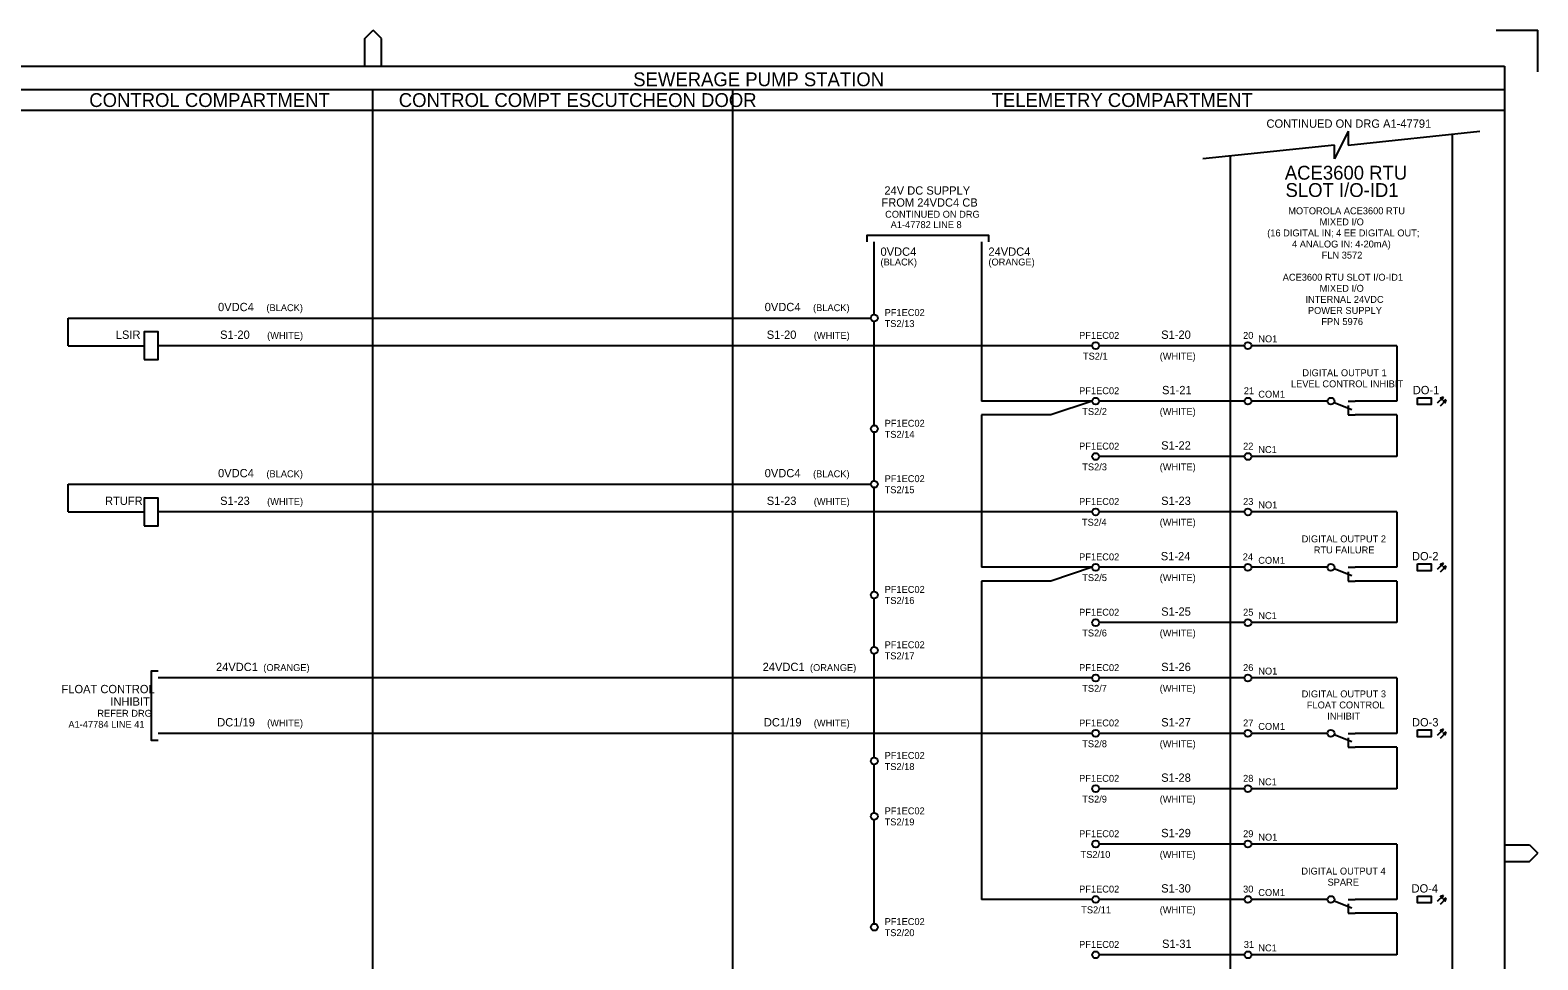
# Model space of a CAD drawing. Extents: x 0 to 841, y 0 to 594.
# Drawn here: x 296 to 841, y 258 to 594 of the extents above; entities that cross this region are included whole.
import ezdxf

# ---------------------------------------------------------------- set-up
doc = ezdxf.new("R2010")
doc.units = 0
for name, color, linetype in [('A1BORDER', 7, 'Continuous'), ('Level 1', 7, 'Continuous'), ('Level 10', 7, 'Continuous'), ('Level 2', 7, 'Continuous')]:
    doc.layers.add(name, color=color, linetype=linetype)

msp = doc.modelspace()

# ---------------------------------------------------------------- linework, layer by layer
at = {"layer": 'A1BORDER'}
for p, q in [((417.19, 591), (420.19, 594)), ((423.19, 591), (420.19, 594)), ((826, 594), (841, 594)), ((841, 579), (841, 594)), ((417.19, 581), (417.19, 591)), ((423.19, 581), (423.19, 591)), ((28, 581), (829, 581)), ((829, 581), (829, 15)), ((829, 299.76), (838, 299.76)), ((838, 299.76), (841, 296.76)), ((838, 293.76), (841, 296.76)), ((829, 293.76), (838, 293.76))]:
    msp.add_line(p, q, dxfattribs=at)
at = {"layer": 'Level 1'}
for p, q in [((829, 572.5), (160, 572.5)), ((420, 572.5), (420, 57)), ((550, 572.5), (550, 57)), ((829, 565), (160, 565)), ((772.5, 557.5), (767.5, 547.5)), ((772.5, 557.5), (772.5, 552.5)), ((772.5, 552.5), (820, 557.5)), ((767.5, 552.5), (720, 547.5)), ((767.5, 547.5), (767.5, 552.5)), ((601.25, 491.25), (601.25, 517.5)), ((640, 517.5), (640, 460)), ((310, 490), (600, 490)), ((310, 480), (310, 490)), ((601.25, 451.25), (601.25, 488.75)), ((310, 480), (337.5, 480)), ((680, 480), (342.5, 480)), ((735, 480), (682.5, 480)), ((790, 480), (737.5, 480)), ((790, 480), (790, 460)), ((680, 460), (640, 460)), ((680, 460), (665, 455)), ((735, 460), (682.5, 460)), ((765, 460), (737.5, 460)), ((790, 460), (775, 460)), ((665, 455), (640, 455)), ((640, 455), (640, 400)), ((790, 455), (775, 455)), ((790, 455), (790, 440)), ((601.25, 431.25), (601.25, 448.75)), ((735, 440), (682.5, 440)), ((790, 440), (737.5, 440)), ((310, 430), (600, 430)), ((310, 420), (310, 430)), ((601.25, 391.25), (601.25, 428.75)), ((310, 420), (337.5, 420)), ((680, 420), (342.5, 420)), ((735, 420), (682.5, 420)), ((790, 420), (737.5, 420)), ((790, 420), (790, 400)), ((680, 400), (640, 400)), ((680, 400), (665, 395)), ((735, 400), (682.5, 400)), ((765, 400), (737.5, 400)), ((790, 400), (775, 400)), ((665, 395), (640, 395)), ((640, 395), (640, 280)), ((790, 395), (775, 395)), ((790, 395), (790, 380)), ((601.25, 371.25), (601.25, 388.75)), ((735, 380), (682.5, 380)), ((790, 380), (737.5, 380)), ((601.25, 331.25), (601.25, 368.75)), ((680, 360), (342.5, 360)), ((735, 360), (682.5, 360)), ((790, 360), (737.5, 360)), ((790, 360), (790, 340)), ((680, 340), (342.5, 340)), ((735, 340), (682.5, 340)), ((765, 340), (737.5, 340)), ((790, 340), (775, 340)), ((790, 335), (775, 335)), ((790, 335), (790, 320)), ((601.25, 311.25), (601.25, 328.75)), ((735, 320), (682.5, 320)), ((790, 320), (737.5, 320)), ((601.25, 271.25), (601.25, 308.75)), ((735, 300), (682.5, 300)), ((790, 300), (737.5, 300)), ((790, 300), (790, 280)), ((680, 280), (640, 280)), ((735, 280), (682.5, 280)), ((765, 280), (737.5, 280)), ((790, 280), (775, 280)), ((790, 275), (775, 275)), ((790, 275), (790, 260)), ((735, 260), (682.5, 260)), ((790, 260), (737.5, 260))]:
    msp.add_line(p, q, dxfattribs=at)
for points in [[(810, 556.45), (810, 80), (730, 80), (730, 548.55)], [(598.75, 517.5), (598.75, 520), (642.5, 520), (642.5, 517.5)], [(342.5, 362.5), (340, 362.5), (340, 337.5), (342.5, 337.5)]]:
    msp.add_lwpolyline(points, dxfattribs=at)
for points in [[(337.5, 475), (342.5, 475), (342.5, 485), (337.5, 485)], [(797.5, 461.25), (802.5, 461.25), (802.5, 458.75), (797.5, 458.75)], [(337.5, 415), (342.5, 415), (342.5, 425), (337.5, 425)], [(797.5, 401.25), (802.5, 401.25), (802.5, 398.75), (797.5, 398.75)], [(797.5, 341.25), (802.5, 341.25), (802.5, 338.75), (797.5, 338.75)], [(797.5, 281.25), (802.5, 281.25), (802.5, 278.75), (797.5, 278.75)]]:
    msp.add_lwpolyline(points, close=True, dxfattribs=at)
at = {"layer": 'Level 10'}
for p, q in [((767.41, 459.54), (773.75, 457)), ((772.5, 460), (775, 460)), ((772.5, 458.37), (772.5, 455)), ((804.73, 459.35), (806.86, 461.48)), ((805.79, 458.29), (807.91, 460.42)), ((805.96, 461.07), (806.67, 461.07)), ((806, 460.92), (806.61, 460.92)), ((806.14, 460.77), (806.53, 460.77)), ((806.29, 461.22), (806.74, 461.22)), ((806.3, 460.62), (806.47, 460.62)), ((806.62, 461.37), (806.81, 461.37)), ((807.02, 460.01), (807.73, 460.01)), ((807.06, 459.86), (807.66, 459.86)), ((807.21, 459.71), (807.6, 459.71)), ((807.35, 460.16), (807.8, 460.16)), ((807.36, 459.56), (807.53, 459.56)), ((807.68, 460.31), (807.87, 460.31)), ((772.5, 455), (775, 455)), ((767.41, 399.54), (773.75, 397)), ((772.5, 400), (775, 400)), ((772.5, 398.37), (772.5, 395)), ((804.73, 399.35), (806.86, 401.48)), ((805.79, 398.29), (807.91, 400.42)), ((805.96, 401.07), (806.67, 401.07)), ((806, 400.92), (806.61, 400.92)), ((806.14, 400.77), (806.53, 400.77)), ((806.29, 401.22), (806.74, 401.22)), ((806.3, 400.62), (806.47, 400.62)), ((806.62, 401.37), (806.81, 401.37)), ((807.02, 400.01), (807.73, 400.01)), ((807.06, 399.86), (807.66, 399.86)), ((807.21, 399.71), (807.6, 399.71)), ((807.35, 400.16), (807.8, 400.16)), ((807.36, 399.56), (807.53, 399.56)), ((807.68, 400.31), (807.87, 400.31)), ((772.5, 395), (775, 395)), ((767.41, 339.54), (773.75, 337)), ((772.5, 340), (775, 340)), ((772.5, 338.37), (772.5, 335)), ((804.73, 339.35), (806.86, 341.48)), ((805.79, 338.29), (807.91, 340.42)), ((805.96, 341.07), (806.67, 341.07)), ((806, 340.92), (806.61, 340.92)), ((806.14, 340.77), (806.53, 340.77)), ((806.29, 341.22), (806.74, 341.22)), ((806.3, 340.62), (806.47, 340.62)), ((806.62, 341.37), (806.81, 341.37)), ((807.02, 340.01), (807.73, 340.01)), ((807.06, 339.86), (807.66, 339.86)), ((807.21, 339.71), (807.6, 339.71)), ((807.35, 340.16), (807.8, 340.16)), ((807.36, 339.56), (807.53, 339.56)), ((807.68, 340.31), (807.87, 340.31)), ((772.5, 335), (775, 335)), ((767.41, 279.54), (773.75, 277)), ((772.5, 280), (775, 280)), ((772.5, 278.37), (772.5, 275)), ((804.73, 279.35), (806.86, 281.48)), ((805.79, 278.29), (807.91, 280.42)), ((805.96, 281.07), (806.67, 281.07)), ((806, 280.92), (806.61, 280.92)), ((806.14, 280.77), (806.53, 280.77)), ((806.29, 281.22), (806.74, 281.22)), ((806.3, 280.62), (806.47, 280.62)), ((806.62, 281.37), (806.81, 281.37)), ((807.02, 280.01), (807.73, 280.01)), ((807.06, 279.86), (807.66, 279.86)), ((807.21, 279.71), (807.6, 279.71)), ((807.35, 280.16), (807.8, 280.16)), ((807.36, 279.56), (807.53, 279.56)), ((807.68, 280.31), (807.87, 280.31)), ((772.5, 275), (775, 275))]:
    msp.add_line(p, q, dxfattribs=at)
for points in [[(806.86, 461.48), (805.88, 461.04), (806.41, 460.5)], [(807.91, 460.42), (806.94, 459.98), (807.48, 459.44)], [(806.86, 401.48), (805.88, 401.04), (806.41, 400.5)], [(807.91, 400.42), (806.94, 399.98), (807.48, 399.44)], [(806.86, 341.48), (805.88, 341.04), (806.41, 340.5)], [(807.91, 340.42), (806.94, 339.98), (807.48, 339.44)], [(806.86, 281.48), (805.88, 281.04), (806.41, 280.5)], [(807.91, 280.42), (806.94, 279.98), (807.48, 279.44)]]:
    msp.add_lwpolyline(points, close=True, dxfattribs=at)
for centre in [(601.25, 490), (681.25, 480), (736.25, 480), (681.25, 460), (736.25, 460), (766.25, 460), (601.25, 450), (681.25, 440), (736.25, 440), (601.25, 430), (681.25, 420), (736.25, 420), (681.25, 400), (736.25, 400), (766.25, 400), (601.25, 390), (681.25, 380), (736.25, 380), (601.25, 370), (681.25, 360), (736.25, 360), (681.25, 340), (736.25, 340), (766.25, 340), (601.25, 330), (681.25, 320), (736.25, 320), (601.25, 310), (681.25, 300), (736.25, 300), (681.25, 280), (736.25, 280), (766.25, 280), (601.25, 270), (681.25, 260), (736.25, 260)]:
    msp.add_circle(centre, 1.25, dxfattribs=at)

# ---------------------------------------------------------------- texts
at = {"layer": 'Level 1'}
for s, height, p in [('SEWERAGE PUMP STATION', 5, (514.16, 573.75)), ('CONTROL COMPARTMENT', 5, (317.64, 566.25)), ('CONTROL COMPT ESCUTCHEON DOOR', 5, (429.47, 566.25)), ('TELEMETRY COMPARTMENT', 5, (643.66, 566.25)), ('CONTINUED ON DRG A1-47791', 3, (742.96, 558.75)), ('ACE3600 RTU', 5, (749.58, 540)), ('24V DC SUPPLY', 3, (604.91, 534.59)), ('SLOT I/O-ID1', 5, (749.83, 533.75)), ('FROM 24VDC4 CB', 3, (603.86, 530.25)), ('CONTINUED ON DRG', 2.5, (605.18, 526.25)), ('MOTOROLA ACE3600 RTU', 2.5, (750.83, 527.5)), ('A1-47782 LINE 8', 2.5, (607.18, 522.5)), ('MIXED I/O', 2.5, (762.16, 523.5)), ('(16 DIGITAL IN; 4 EE DIGITAL OUT; ', 2.5, (743.23, 519.5)), ('4 ANALOG IN: 4-20mA)', 2.5, (752.19, 515.5)), ('0VDC4', 3, (603.5, 512.5)), ('24VDC4', 3, (642.5, 512.5)), ('FLN 3572', 2.5, (762.9, 511.5)), ('(BLACK)', 2.5, (603.5, 509)), ('(ORANGE)', 2.5, (642.5, 509)), ('ACE3600 RTU SLOT I/O-ID1', 2.5, (748.83, 503.5)), ('MIXED I/O', 2.5, (762.16, 499.5)), ('INTERNAL 24VDC', 2.5, (757.05, 495.5)), ('0VDC4', 3, (364.17, 492.5)), ('(BLACK)', 2.5, (381.65, 492.5)), ('0VDC4', 3, (561.67, 492.5)), ('(BLACK)', 2.5, (579.15, 492.5)), ('PF1EC02', 2.5, (605, 490.75)), ('POWER SUPPLY', 2.5, (757.92, 491.5)), ('LSIR', 3, (327.23, 482.5)), ('S1-20', 3, (364.92, 482.5)), ('(WHITE)', 2.5, (381.9, 482.5)), ('S1-20', 3, (562.42, 482.5)), ('(WHITE)', 2.5, (579.4, 482.5)), ('TS2/13', 2.5, (605, 486.75)), ('PF1EC02', 2.5, (675.27, 482.5)), ('S1-20', 3, (704.92, 482.5)), ('20', 2.5, (734.51, 482.5)), ('FPN 5976', 2.5, (762.78, 487.5)), ('NO1', 2.5, (740, 481.25)), ('TS2/1', 2.5, (676.65, 475)), ('(WHITE)', 2.5, (704.39, 475)), ('DIGITAL OUTPUT 1', 2.5, (755.93, 469)), ('PF1EC02', 2.5, (675.27, 462.5)), ('S1-21', 3, (705.22, 462.5)), ('21', 2.5, (734.76, 462.5)), ('COM1', 2.5, (740, 461.25)), ('LEVEL CONTROL INHIBIT', 2.5, (751.82, 465)), ('DO-1', 3, (795.82, 462.5)), ('TS2/2', 2.5, (676.4, 455)), ('(WHITE)', 2.5, (704.39, 455)), ('PF1EC02', 2.5, (675.27, 442.5)), ('S1-22', 3, (704.92, 442.5)), ('22', 2.5, (734.51, 442.5)), ('NC1', 2.5, (740, 441.25)), ('TS2/3', 2.5, (676.4, 435)), ('(WHITE)', 2.5, (704.39, 435)), ('0VDC4', 3, (364.17, 432.5)), ('(BLACK)', 2.5, (381.65, 432.5)), ('0VDC4', 3, (561.67, 432.5)), ('(BLACK)', 2.5, (579.15, 432.5)), ('RTUFR', 3, (323.34, 422.5)), ('S1-23', 3, (364.92, 422.5)), ('(WHITE)', 2.5, (381.9, 422.5)), ('S1-23', 3, (562.42, 422.5)), ('(WHITE)', 2.5, (579.4, 422.5)), ('PF1EC02', 2.5, (675.27, 422.5)), ('S1-23', 3, (704.92, 422.5)), ('23', 2.5, (734.51, 422.5)), ('NO1', 2.5, (740, 421.25)), ('TS2/4', 2.5, (676.28, 415)), ('(WHITE)', 2.5, (704.39, 415)), ('DIGITAL OUTPUT 2', 2.5, (755.68, 409)), ('PF1EC02', 2.5, (675.27, 402.5)), ('S1-24', 3, (704.77, 402.5)), ('24', 2.5, (734.38, 402.5)), ('COM1', 2.5, (740, 401.25)), ('RTU FAILURE', 2.5, (760.04, 405)), ('DO-2', 3, (795.52, 402.5)), ('TS2/5', 2.5, (676.4, 395)), ('(WHITE)', 2.5, (704.39, 395)), ('PF1EC02', 2.5, (675.27, 382.5)), ('S1-25', 3, (704.92, 382.5)), ('25', 2.5, (734.51, 382.5)), ('NC1', 2.5, (740, 381.25)), ('TS2/6', 2.5, (676.4, 375)), ('(WHITE)', 2.5, (704.39, 375)), ('24VDC1', 3, (363.42, 362.5)), ('(ORANGE)', 2.5, (380.53, 362.5)), ('24VDC1', 3, (560.93, 362.5)), ('(ORANGE)', 2.5, (578.03, 362.5)), ('PF1EC02', 2.5, (675.27, 362.5)), ('S1-26', 3, (704.92, 362.5)), ('26', 2.5, (734.51, 362.5)), ('NO1', 2.5, (740, 361.25)), ('FLOAT CONTROL', 3, (307.62, 354.5)), ('TS2/7', 2.5, (676.4, 355)), ('(WHITE)', 2.5, (704.39, 355)), ('DIGITAL OUTPUT 3', 2.5, (755.68, 353)), ('INHIBIT', 3, (325.25, 350)), ('FLOAT CONTROL', 2.5, (757.55, 349)), ('A1-47784 LINE 41', 2.5, (310.11, 342)), ('REFER DRG', 2.5, (320.57, 346)), ('DC1/19', 3, (363.87, 342.5)), ('(WHITE)', 2.5, (381.89, 342.5)), ('DC1/19', 3, (561.37, 342.5)), ('(WHITE)', 2.5, (579.4, 342.5)), ('PF1EC02', 2.5, (675.27, 342.5)), ('S1-27', 3, (704.92, 342.5)), ('27', 2.5, (734.51, 342.5)), ('COM1', 2.5, (740, 341.25)), ('INHIBIT', 2.5, (764.9, 345)), ('DO-3', 3, (795.52, 342.5)), ('TS2/8', 2.5, (676.4, 335)), ('(WHITE)', 2.5, (704.39, 335)), ('PF1EC02', 2.5, (675.27, 322.5)), ('S1-28', 3, (704.92, 322.5)), ('28', 2.5, (734.51, 322.5)), ('NC1', 2.5, (740, 321.25)), ('TS2/9', 2.5, (676.4, 315)), ('(WHITE)', 2.5, (704.39, 315)), ('S1-29', 3, (704.92, 302.5)), ('PF1EC02', 2.5, (675.27, 302.5)), ('29', 2.5, (734.51, 302.5)), ('NO1', 2.5, (740, 301.25)), ('TS2/10', 2.5, (675.78, 295)), ('(WHITE)', 2.5, (704.39, 295)), ('DIGITAL OUTPUT 4', 2.5, (755.56, 289)), ('PF1EC02', 2.5, (675.27, 282.5)), ('S1-30', 3, (704.92, 282.5)), ('30', 2.5, (734.51, 282.5)), ('COM1', 2.5, (740, 281.25)), ('SPARE', 2.5, (765.02, 285)), ('DO-4', 3, (795.37, 282.5)), ('TS2/11', 2.5, (676.03, 275)), ('(WHITE)', 2.5, (704.39, 275)), ('PF1EC02', 2.5, (675.27, 262.5)), ('S1-31', 3, (705.22, 262.5)), ('31', 2.5, (734.76, 262.5)), ('NC1', 2.5, (740, 261.25))]:
    msp.add_text(s, height=height, dxfattribs=at).set_placement(p)
at = {"layer": 'Level 2'}
for s, p in [('PF1EC02', (605, 450.75)), ('TS2/14', (605, 446.75)), ('PF1EC02', (605, 430.75)), ('TS2/15', (605, 426.75)), ('PF1EC02', (605, 390.75)), ('TS2/16', (605, 386.75)), ('PF1EC02', (605, 370.75)), ('TS2/17', (605, 366.75)), ('PF1EC02', (605, 330.75)), ('TS2/18', (605, 326.75)), ('PF1EC02', (605, 310.75)), ('TS2/19', (605, 306.75)), ('PF1EC02', (605, 270.75)), ('TS2/20', (605, 266.75))]:
    msp.add_text(s, height=2.5, dxfattribs=at).set_placement(p)

doc.saveas('drawing.dxf')
